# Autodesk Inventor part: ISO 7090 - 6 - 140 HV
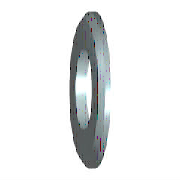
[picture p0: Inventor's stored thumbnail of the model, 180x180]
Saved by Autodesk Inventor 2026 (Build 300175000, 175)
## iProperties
Created: 2013-02
Part Number: ISO 7090 - 6 - 140 HV
Material: Stainless Steel
Description: Plain washers, charmfered - Normal series - Product grade A
Document SubType Name: Modeling
Standard: ISO 7090
Designer: Cadskolen
Standard Revision: Second edition 2000-06-01
Standards Organization: ISO
Language: en-US
Size Designation: 6 - 140 HV
Categories: <MemberInstance><Categories><Category DisplayName="Fasteners" InternalName="e4da775c-781d-43d5-af7c-5136215cf5a6" Mnemonic="FSTN"><Category DisplayName="Washers
Density: 8.08 g/cm^3
Appearance: Semi-Polished
IsCustomPart: 0
Author: Cadskolen
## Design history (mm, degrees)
body "Solid1"
sketch "Sketch"
  geometry: C1 r 6 at (0, 0); C2 r 3.2 at (0, 0); 1 further point
  constraints: 2 centre point, 2 coincident
  dimensions: "d0" = 6.4 diameter of C2 (= SD1); "d1" = 12 diameter of C1 (= SD2)
extrude "Body" new body sketch "Sketch" distance "d2" = 1.6 (= SD); taper "d3" = 0 deg
workaxis "Work Axis1"
workplane "Work Plane1"
chamfer "Chamfer" distance "d4" = 0.8 (= PHH); stored, may be unused: angle "d5" = 45 deg, second distance "d8" = 0.8 (= PHH)
other parameters: "SD1" = 6.4 [user parameter; used in 1 equation term], "SD2" = 12 [user parameter; used in 1 equation term], "SD" = 1.6 [user parameter; used in 1 equation term], "PHH" = 0.8 [user parameter; used in 2 equation terms], "FAWI" = 45 deg [user parameter], "d6" = 0, "d7" = 0, "d9" = 0, "d10" = 0, "NND" = 6 [user parameter]
